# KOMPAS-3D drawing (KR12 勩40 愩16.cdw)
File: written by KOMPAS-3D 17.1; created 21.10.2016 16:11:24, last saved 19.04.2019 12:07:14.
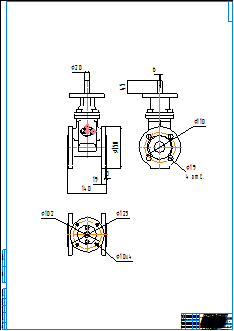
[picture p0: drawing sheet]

Sheet 1: A0, portrait

Title block, sheet 1: name: KR12 Ду40 Ру16; material: Внимание! Данный продукт является объектом авторского права ООО «Торговый Дом АДЛ». / Запрещается изменение, копирование, распространение / (в том числе путем копирования на другие сайты и ресурсы в Интернете) / или любое иное использование информации и объектов без предварительного / согласия правообладателя (ООО «Торговый Дом АДЛ»).; mass: 14,1; sheets: 1; organisation: ООО "Торговый дом АДЛ"; sheet format: A0; stored path: \\adlc.lan\data\АДЛ_ПКД\3D-модели\ADL production\Клиновые задвижки серии KR ГРАНАР\Клиновые задвижки KR12\KOMPAS 2D\KR12 Ду40 Ру16.cdw

Views: Спереди 4, Проекционный вид 5, Проекционный вид 6
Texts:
  Klimkovich
  ADL
  Symbol type A
Dimensions and other numbers on the sheet: 19; 20; 125; 102; 10; 140; 3; 110; 4 отв.; 45; 6; 150; 1:1; 1; 14,1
